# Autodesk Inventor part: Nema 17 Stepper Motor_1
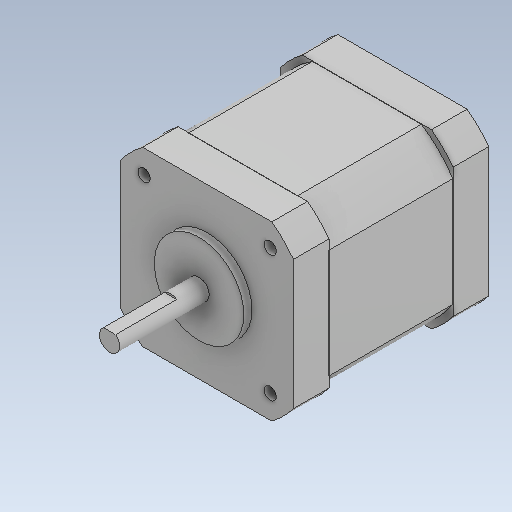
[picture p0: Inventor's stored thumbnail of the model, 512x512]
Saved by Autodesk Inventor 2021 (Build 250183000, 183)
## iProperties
Created: 2026-10
Part Number: Nema 17 Stepper Motor_1
Material: Generic
Document SubType Name: Modeling
Designer: hp
Density: 1 g/cm^3
Appearance: Default
Author: hp
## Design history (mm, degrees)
feature "Body1"
body "Solid1"
